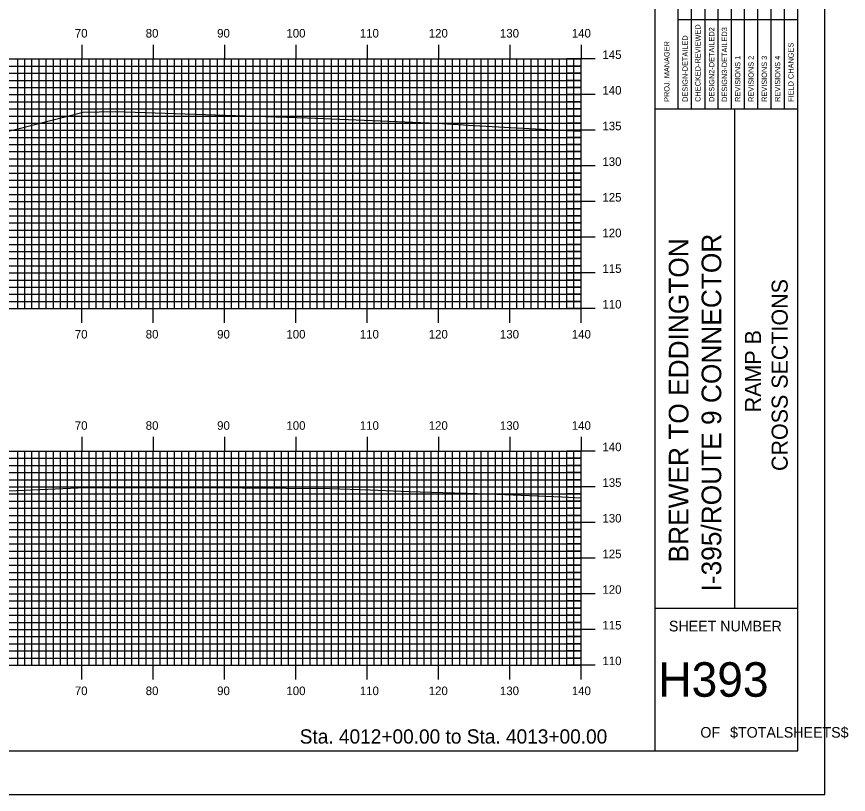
# Model space of a CAD drawing. Extents: x 852934 to 853277, y 364661 to 364881.
# Drawn here: x 853160.6 to 853277.3, y 364661.3 to 364770.3 of the extents above; entities that cross this region are included whole.
import ezdxf

# ---------------------------------------------------------------- set-up
doc = ezdxf.new("R2010")
doc.units = 0
for name, color, linetype in [('BORDER', 7, 'Continuous'), ('H_V ANNOTATION', 7, 'Continuous'), ('MAJOR', 7, 'Continuous'), ('MINOR', 7, 'Continuous'), ('PLOT BOUNDARY', 7, 'Continuous'), ('S_Roadway_Centerline', 7, 'Continuous')]:
    doc.layers.add(name, color=color, linetype=linetype)

msp = doc.modelspace()

# ---------------------------------------------------------------- linework, layer by layer
at = {"layer": 'BORDER'}
for p, q in [((853250.18, 364667.37), (853250.18, 364877.37)), ((853250.18, 364757.38), (853270.18, 364757.38)), ((853261.36, 364687.38), (853261.36, 364757.38)), ((853250.18, 364687.38), (853270.18, 364687.38))]:
    msp.add_line(p, q, dxfattribs=at)
msp.add_lwpolyline([(852950.18, 364667.37), (853270.18, 364667.37), (853270.18, 364877.37), (852950.18, 364877.37)], close=True, dxfattribs=at)
for points in [[(853255.28, 364757.38), (853255.28, 364792.38)], [(853257.14, 364792.38), (853257.14, 364757.38)], [(853259, 364757.38), (853259, 364792.38)], [(853260.87, 364757.38), (853260.87, 364792.38)], [(853262.73, 364757.38), (853262.73, 364792.38)], [(853264.59, 364757.38), (853264.59, 364792.38)], [(853266.46, 364757.38), (853266.46, 364792.38)], [(853268.32, 364757.38), (853268.32, 364792.38)], [(853253.41, 364757.38), (853253.41, 364790.96)], [(853253.41, 364769.88), (853270.18, 364769.88)]]:
    msp.add_lwpolyline(points, dxfattribs=at)
at = {"layer": 'MAJOR'}
for p, q in [((853169.78, 364766.37), (853169.78, 364764.37)), ((853179.78, 364766.37), (853179.78, 364764.37)), ((853189.78, 364766.37), (853189.78, 364764.37)), ((853199.78, 364766.37), (853199.78, 364764.37)), ((853209.78, 364766.37), (853209.78, 364764.37)), ((853219.78, 364766.37), (853219.78, 364764.37)), ((853229.78, 364766.37), (853229.78, 364764.37)), ((853239.78, 364766.37), (853239.78, 364764.37)), ((852959.78, 364764.37), (853239.78, 364764.37)), ((852959.78, 364764.37), (853239.78, 364764.37)), ((853169.78, 364729.37), (853169.78, 364764.37)), ((853179.78, 364729.37), (853179.78, 364764.37)), ((853189.78, 364729.37), (853189.78, 364764.37)), ((853199.78, 364729.37), (853199.78, 364764.37)), ((853209.78, 364729.37), (853209.78, 364764.37)), ((853219.78, 364729.37), (853219.78, 364764.37)), ((853229.78, 364729.37), (853229.78, 364764.37)), ((853241.79, 364764.37), (853237.78, 364764.37)), ((853239.78, 364729.37), (853239.78, 364764.37)), ((853239.78, 364729.37), (853239.78, 364764.37)), ((852959.78, 364759.37), (853239.78, 364759.37)), ((853241.79, 364759.37), (853237.78, 364759.37)), ((852959.78, 364754.37), (853239.78, 364754.37)), ((853241.79, 364754.37), (853237.78, 364754.37)), ((852959.78, 364749.37), (853239.78, 364749.37)), ((853241.79, 364749.37), (853237.78, 364749.37)), ((852959.78, 364744.37), (853239.78, 364744.37)), ((853241.79, 364744.37), (853237.78, 364744.37)), ((852959.78, 364739.37), (853239.78, 364739.37)), ((853241.79, 364739.37), (853237.78, 364739.37)), ((852959.78, 364734.37), (853239.78, 364734.37)), ((853241.79, 364734.37), (853237.78, 364734.37)), ((852959.78, 364729.37), (853239.78, 364729.37)), ((852959.78, 364729.37), (853239.78, 364729.37)), ((853169.78, 364727.37), (853169.78, 364729.37)), ((853179.78, 364727.37), (853179.78, 364729.37)), ((853189.78, 364727.37), (853189.78, 364729.37)), ((853199.78, 364727.37), (853199.78, 364729.37)), ((853209.78, 364727.37), (853209.78, 364729.37)), ((853219.78, 364727.37), (853219.78, 364729.37)), ((853229.78, 364727.37), (853229.78, 364729.37)), ((853241.79, 364729.37), (853237.78, 364729.37)), ((853239.78, 364727.37), (853239.78, 364729.37)), ((853169.78, 364711.37), (853169.78, 364709.37)), ((853179.78, 364711.37), (853179.78, 364709.37)), ((853189.78, 364711.37), (853189.78, 364709.37)), ((853199.78, 364711.37), (853199.78, 364709.37)), ((853209.78, 364711.37), (853209.78, 364709.37)), ((853219.78, 364711.37), (853219.78, 364709.37)), ((853229.78, 364711.37), (853229.78, 364709.37)), ((853239.78, 364711.37), (853239.78, 364709.37)), ((852959.78, 364709.37), (853239.78, 364709.37)), ((852959.78, 364709.37), (853239.78, 364709.37)), ((853169.78, 364679.37), (853169.78, 364709.37)), ((853179.78, 364679.37), (853179.78, 364709.37)), ((853189.78, 364679.37), (853189.78, 364709.37)), ((853199.78, 364679.37), (853199.78, 364709.37)), ((853209.78, 364679.37), (853209.78, 364709.37)), ((853219.78, 364679.37), (853219.78, 364709.37)), ((853229.78, 364679.37), (853229.78, 364709.37)), ((853241.79, 364709.37), (853237.78, 364709.37)), ((853239.78, 364679.37), (853239.78, 364709.37)), ((853239.78, 364679.37), (853239.78, 364709.37)), ((852959.78, 364704.37), (853239.78, 364704.37)), ((853241.79, 364704.37), (853237.78, 364704.37)), ((852959.78, 364699.37), (853239.78, 364699.37)), ((853241.79, 364699.37), (853237.78, 364699.37)), ((852959.78, 364694.37), (853239.78, 364694.37)), ((853241.79, 364694.37), (853237.78, 364694.37)), ((852959.78, 364689.37), (853239.78, 364689.37)), ((853241.79, 364689.37), (853237.78, 364689.37)), ((852959.78, 364684.37), (853239.78, 364684.37)), ((853241.79, 364684.37), (853237.78, 364684.37)), ((852959.78, 364679.37), (853239.78, 364679.37)), ((852959.78, 364679.37), (853239.78, 364679.37)), ((853169.78, 364677.37), (853169.78, 364679.37)), ((853179.78, 364677.37), (853179.78, 364679.37)), ((853189.78, 364677.37), (853189.78, 364679.37)), ((853199.78, 364677.37), (853199.78, 364679.37)), ((853209.78, 364677.37), (853209.78, 364679.37)), ((853219.78, 364677.37), (853219.78, 364679.37)), ((853229.78, 364677.37), (853229.78, 364679.37)), ((853241.79, 364679.37), (853237.78, 364679.37)), ((853239.78, 364677.37), (853239.78, 364679.37))]:
    msp.add_line(p, q, dxfattribs=at)
at = {"layer": 'MINOR'}
for p, q in [((853160.78, 364729.37), (853160.78, 364764.37)), ((853161.78, 364729.37), (853161.78, 364764.37)), ((853162.78, 364729.37), (853162.78, 364764.37)), ((853163.78, 364729.37), (853163.78, 364764.37)), ((853164.78, 364729.37), (853164.78, 364764.37)), ((853165.78, 364729.37), (853165.78, 364764.37)), ((853166.78, 364729.37), (853166.78, 364764.37)), ((853167.78, 364729.37), (853167.78, 364764.37)), ((853168.78, 364729.37), (853168.78, 364764.37)), ((853170.78, 364729.37), (853170.78, 364764.37)), ((853171.78, 364729.37), (853171.78, 364764.37)), ((853172.78, 364729.37), (853172.78, 364764.37)), ((853173.78, 364729.37), (853173.78, 364764.37)), ((853174.78, 364729.37), (853174.78, 364764.37)), ((853175.78, 364729.37), (853175.78, 364764.37)), ((853176.78, 364729.37), (853176.78, 364764.37)), ((853177.78, 364729.37), (853177.78, 364764.37)), ((853178.78, 364729.37), (853178.78, 364764.37)), ((853180.78, 364729.37), (853180.78, 364764.37)), ((853181.78, 364729.37), (853181.78, 364764.37)), ((853182.78, 364729.37), (853182.78, 364764.37)), ((853183.78, 364729.37), (853183.78, 364764.37)), ((853184.78, 364729.37), (853184.78, 364764.37)), ((853185.78, 364729.37), (853185.78, 364764.37)), ((853186.78, 364729.37), (853186.78, 364764.37)), ((853187.78, 364729.37), (853187.78, 364764.37)), ((853188.78, 364729.37), (853188.78, 364764.37)), ((853190.78, 364729.37), (853190.78, 364764.37)), ((853191.78, 364729.37), (853191.78, 364764.37)), ((853192.78, 364729.37), (853192.78, 364764.37)), ((853193.78, 364729.37), (853193.78, 364764.37)), ((853194.78, 364729.37), (853194.78, 364764.37)), ((853195.78, 364729.37), (853195.78, 364764.37)), ((853196.78, 364729.37), (853196.78, 364764.37)), ((853197.78, 364729.37), (853197.78, 364764.37)), ((853198.78, 364729.37), (853198.78, 364764.37)), ((853200.78, 364729.37), (853200.78, 364764.37)), ((853201.78, 364729.37), (853201.78, 364764.37)), ((853202.78, 364729.37), (853202.78, 364764.37)), ((853203.78, 364729.37), (853203.78, 364764.37)), ((853204.78, 364729.37), (853204.78, 364764.37)), ((853205.78, 364729.37), (853205.78, 364764.37)), ((853206.78, 364729.37), (853206.78, 364764.37)), ((853207.78, 364729.37), (853207.78, 364764.37)), ((853208.78, 364729.37), (853208.78, 364764.37)), ((853210.78, 364729.37), (853210.78, 364764.37)), ((853211.78, 364729.37), (853211.78, 364764.37)), ((853212.78, 364729.37), (853212.78, 364764.37)), ((853213.78, 364729.37), (853213.78, 364764.37)), ((853214.78, 364729.37), (853214.78, 364764.37)), ((853215.78, 364729.37), (853215.78, 364764.37)), ((853216.78, 364729.37), (853216.78, 364764.37)), ((853217.78, 364729.37), (853217.78, 364764.37)), ((853218.78, 364729.37), (853218.78, 364764.37)), ((853220.78, 364729.37), (853220.78, 364764.37)), ((853221.78, 364729.37), (853221.78, 364764.37)), ((853222.78, 364729.37), (853222.78, 364764.37)), ((853223.78, 364729.37), (853223.78, 364764.37)), ((853224.78, 364729.37), (853224.78, 364764.37)), ((853225.78, 364729.37), (853225.78, 364764.37)), ((853226.78, 364729.37), (853226.78, 364764.37)), ((853227.78, 364729.37), (853227.78, 364764.37)), ((853228.78, 364729.37), (853228.78, 364764.37)), ((853230.78, 364729.37), (853230.78, 364764.37)), ((853231.78, 364729.37), (853231.78, 364764.37)), ((853232.78, 364729.37), (853232.78, 364764.37)), ((853233.78, 364729.37), (853233.78, 364764.37)), ((853234.78, 364729.37), (853234.78, 364764.37)), ((853235.78, 364729.37), (853235.78, 364764.37)), ((853236.78, 364729.37), (853236.78, 364764.37)), ((853237.78, 364729.37), (853237.78, 364764.37)), ((853238.78, 364729.37), (853238.78, 364764.37)), ((852959.78, 364763.37), (853239.78, 364763.37)), ((853239.78, 364763.37), (853237.78, 364763.37)), ((852959.78, 364762.37), (853239.78, 364762.37)), ((853239.78, 364762.37), (853237.78, 364762.37)), ((852959.78, 364761.37), (853239.78, 364761.37)), ((853239.78, 364761.37), (853237.78, 364761.37)), ((852959.78, 364760.37), (853239.78, 364760.37)), ((853239.78, 364760.37), (853237.78, 364760.37)), ((852959.78, 364758.37), (853239.78, 364758.37)), ((852959.78, 364757.37), (853239.78, 364757.37)), ((853239.78, 364758.37), (853237.78, 364758.37)), ((853239.78, 364757.37), (853237.78, 364757.37)), ((852959.78, 364756.37), (853239.78, 364756.37)), ((853239.78, 364756.37), (853237.78, 364756.37)), ((852959.78, 364755.37), (853239.78, 364755.37)), ((853239.78, 364755.37), (853237.78, 364755.37)), ((852959.78, 364753.37), (853239.78, 364753.37)), ((853239.78, 364753.37), (853237.78, 364753.37)), ((852959.78, 364752.37), (853239.78, 364752.37)), ((853239.78, 364752.37), (853237.78, 364752.37)), ((852959.78, 364751.37), (853239.78, 364751.37)), ((852959.78, 364750.37), (853239.78, 364750.37)), ((853239.78, 364751.37), (853237.78, 364751.37)), ((853239.78, 364750.37), (853237.78, 364750.37)), ((852959.78, 364748.37), (853239.78, 364748.37)), ((853239.78, 364748.37), (853237.78, 364748.37)), ((852959.78, 364747.37), (853239.78, 364747.37)), ((853239.78, 364747.37), (853237.78, 364747.37)), ((852959.78, 364746.37), (853239.78, 364746.37)), ((853239.78, 364746.37), (853237.78, 364746.37)), ((852959.78, 364745.37), (853239.78, 364745.37)), ((853239.78, 364745.37), (853237.78, 364745.37)), ((852959.78, 364743.37), (853239.78, 364743.37)), ((853239.78, 364743.37), (853237.78, 364743.37)), ((852959.78, 364742.37), (853239.78, 364742.37)), ((853239.78, 364742.37), (853237.78, 364742.37)), ((852959.78, 364741.37), (853239.78, 364741.37)), ((853239.78, 364741.37), (853237.78, 364741.37)), ((852959.78, 364740.37), (853239.78, 364740.37)), ((853239.78, 364740.37), (853237.78, 364740.37)), ((852959.78, 364738.37), (853239.78, 364738.37)), ((853239.78, 364738.37), (853237.78, 364738.37)), ((852959.78, 364737.37), (853239.78, 364737.37)), ((852959.78, 364736.37), (853239.78, 364736.37)), ((853239.78, 364737.37), (853237.78, 364737.37)), ((853239.78, 364736.37), (853237.78, 364736.37)), ((852959.78, 364735.37), (853239.78, 364735.37)), ((853239.78, 364735.37), (853237.78, 364735.37)), ((852959.78, 364733.37), (853239.78, 364733.37)), ((853239.78, 364733.37), (853237.78, 364733.37)), ((852959.78, 364732.37), (853239.78, 364732.37)), ((853239.78, 364732.37), (853237.78, 364732.37)), ((852959.78, 364731.37), (853239.78, 364731.37)), ((853239.78, 364731.37), (853237.78, 364731.37)), ((852959.78, 364730.37), (853239.78, 364730.37)), ((853239.78, 364730.37), (853237.78, 364730.37)), ((852959.78, 364708.37), (853239.78, 364708.37)), ((853160.78, 364679.37), (853160.78, 364709.37)), ((853161.78, 364679.37), (853161.78, 364709.37)), ((853162.78, 364679.37), (853162.78, 364709.37)), ((853163.78, 364679.37), (853163.78, 364709.37)), ((853164.78, 364679.37), (853164.78, 364709.37)), ((853165.78, 364679.37), (853165.78, 364709.37)), ((853166.78, 364679.37), (853166.78, 364709.37)), ((853167.78, 364679.37), (853167.78, 364709.37)), ((853168.78, 364679.37), (853168.78, 364709.37)), ((853170.78, 364679.37), (853170.78, 364709.37)), ((853171.78, 364679.37), (853171.78, 364709.37)), ((853172.78, 364679.37), (853172.78, 364709.37)), ((853173.78, 364679.37), (853173.78, 364709.37)), ((853174.78, 364679.37), (853174.78, 364709.37)), ((853175.78, 364679.37), (853175.78, 364709.37)), ((853176.78, 364679.37), (853176.78, 364709.37)), ((853177.78, 364679.37), (853177.78, 364709.37)), ((853178.78, 364679.37), (853178.78, 364709.37)), ((853180.78, 364679.37), (853180.78, 364709.37)), ((853181.78, 364679.37), (853181.78, 364709.37)), ((853182.78, 364679.37), (853182.78, 364709.37)), ((853183.78, 364679.37), (853183.78, 364709.37)), ((853184.78, 364679.37), (853184.78, 364709.37)), ((853185.78, 364679.37), (853185.78, 364709.37)), ((853186.78, 364679.37), (853186.78, 364709.37)), ((853187.78, 364679.37), (853187.78, 364709.37)), ((853188.78, 364679.37), (853188.78, 364709.37)), ((853190.78, 364679.37), (853190.78, 364709.37)), ((853191.78, 364679.37), (853191.78, 364709.37)), ((853192.78, 364679.37), (853192.78, 364709.37)), ((853193.78, 364679.37), (853193.78, 364709.37)), ((853194.78, 364679.37), (853194.78, 364709.37)), ((853195.78, 364679.37), (853195.78, 364709.37)), ((853196.78, 364679.37), (853196.78, 364709.37)), ((853197.78, 364679.37), (853197.78, 364709.37)), ((853198.78, 364679.37), (853198.78, 364709.37)), ((853200.78, 364679.37), (853200.78, 364709.37)), ((853201.78, 364679.37), (853201.78, 364709.37)), ((853202.78, 364679.37), (853202.78, 364709.37)), ((853203.78, 364679.37), (853203.78, 364709.37)), ((853204.78, 364679.37), (853204.78, 364709.37)), ((853205.78, 364679.37), (853205.78, 364709.37)), ((853206.78, 364679.37), (853206.78, 364709.37)), ((853207.78, 364679.37), (853207.78, 364709.37)), ((853208.78, 364679.37), (853208.78, 364709.37)), ((853210.78, 364679.37), (853210.78, 364709.37)), ((853211.78, 364679.37), (853211.78, 364709.37)), ((853212.78, 364679.37), (853212.78, 364709.37)), ((853213.78, 364679.37), (853213.78, 364709.37)), ((853214.78, 364679.37), (853214.78, 364709.37)), ((853215.78, 364679.37), (853215.78, 364709.37)), ((853216.78, 364679.37), (853216.78, 364709.37)), ((853217.78, 364679.37), (853217.78, 364709.37)), ((853218.78, 364679.37), (853218.78, 364709.37)), ((853220.78, 364679.37), (853220.78, 364709.37)), ((853221.78, 364679.37), (853221.78, 364709.37)), ((853222.78, 364679.37), (853222.78, 364709.37)), ((853223.78, 364679.37), (853223.78, 364709.37)), ((853224.78, 364679.37), (853224.78, 364709.37)), ((853225.78, 364679.37), (853225.78, 364709.37)), ((853226.78, 364679.37), (853226.78, 364709.37)), ((853227.78, 364679.37), (853227.78, 364709.37)), ((853228.78, 364679.37), (853228.78, 364709.37)), ((853230.78, 364679.37), (853230.78, 364709.37)), ((853231.78, 364679.37), (853231.78, 364709.37)), ((853232.78, 364679.37), (853232.78, 364709.37)), ((853233.78, 364679.37), (853233.78, 364709.37)), ((853234.78, 364679.37), (853234.78, 364709.37)), ((853235.78, 364679.37), (853235.78, 364709.37)), ((853236.78, 364679.37), (853236.78, 364709.37)), ((853237.78, 364679.37), (853237.78, 364709.37)), ((853239.78, 364708.37), (853237.78, 364708.37)), ((853238.78, 364679.37), (853238.78, 364709.37)), ((852959.78, 364707.37), (853239.78, 364707.37)), ((853239.78, 364707.37), (853237.78, 364707.37)), ((852959.78, 364706.37), (853239.78, 364706.37)), ((853239.78, 364706.37), (853237.78, 364706.37)), ((852959.78, 364705.37), (853239.78, 364705.37)), ((853239.78, 364705.37), (853237.78, 364705.37)), ((852959.78, 364703.37), (853239.78, 364703.37)), ((853239.78, 364703.37), (853237.78, 364703.37)), ((852959.78, 364702.37), (853239.78, 364702.37)), ((852959.78, 364701.37), (853239.78, 364701.37)), ((853239.78, 364702.37), (853237.78, 364702.37)), ((853239.78, 364701.37), (853237.78, 364701.37)), ((852959.78, 364700.37), (853239.78, 364700.37)), ((853239.78, 364700.37), (853237.78, 364700.37)), ((852959.78, 364698.37), (853239.78, 364698.37)), ((853239.78, 364698.37), (853237.78, 364698.37)), ((852959.78, 364697.37), (853239.78, 364697.37)), ((853239.78, 364697.37), (853237.78, 364697.37)), ((852959.78, 364696.37), (853239.78, 364696.37)), ((853239.78, 364696.37), (853237.78, 364696.37)), ((852959.78, 364695.37), (853239.78, 364695.37)), ((853239.78, 364695.37), (853237.78, 364695.37)), ((852959.78, 364693.37), (853239.78, 364693.37)), ((853239.78, 364693.37), (853237.78, 364693.37)), ((852959.78, 364692.37), (853239.78, 364692.37)), ((853239.78, 364692.37), (853237.78, 364692.37)), ((852959.78, 364691.37), (853239.78, 364691.37)), ((853239.78, 364691.37), (853237.78, 364691.37)), ((852959.78, 364690.37), (853239.78, 364690.37)), ((853239.78, 364690.37), (853237.78, 364690.37)), ((852959.78, 364688.37), (853239.78, 364688.37)), ((853239.78, 364688.37), (853237.78, 364688.37)), ((852959.78, 364687.37), (853239.78, 364687.37)), ((852959.78, 364686.37), (853239.78, 364686.37)), ((853239.78, 364687.37), (853237.78, 364687.37)), ((853239.78, 364686.37), (853237.78, 364686.37)), ((852959.78, 364685.37), (853239.78, 364685.37)), ((853239.78, 364685.37), (853237.78, 364685.37)), ((852959.78, 364683.37), (853239.78, 364683.37)), ((853239.78, 364683.37), (853237.78, 364683.37)), ((852959.78, 364682.37), (853239.78, 364682.37)), ((853239.78, 364682.37), (853237.78, 364682.37)), ((852959.78, 364681.37), (853239.78, 364681.37)), ((853239.78, 364681.37), (853237.78, 364681.37)), ((852959.78, 364680.37), (853239.78, 364680.37)), ((853239.78, 364680.37), (853237.78, 364680.37))]:
    msp.add_line(p, q, dxfattribs=at)
at = {"layer": 'PLOT BOUNDARY'}
msp.add_lwpolyline([(852933.99, 364661.25), (853273.99, 364661.25), (853273.99, 364881.25), (852933.99, 364881.25)], close=True, dxfattribs=at)
at = {"layer": 'S_Roadway_Centerline'}
for points in [[(853151.22, 364752.16), (853169.96, 364756.93), (853174.43, 364756.98), (853195.53, 364756.29), (853198.48, 364756.19), (853201.42, 364756.11), (853219.62, 364755.38), (853224.76, 364755.02), (853237.68, 364754.35), (853239.78, 364754.25)], [(853156.26, 364703.66), (853169.25, 364704.21), (853186.17, 364704.29), (853204.54, 364704.12), (853210.2, 364703.93), (853215.62, 364703.73), (853226.79, 364703.39), (853237.16, 364702.97), (853239.78, 364702.82)]]:
    msp.add_lwpolyline(points, dxfattribs=at)

# ---------------------------------------------------------------- texts
at = {"layer": 'BORDER'}
for s, height, p in [('CHECKED-REVIEWED', 0.7455, (853256.54, 364758.35)), ('DESIGN2-DETAILED2', 0.7455, (853258.48, 364758.35)), ('DESIGN3-DETAILED3', 0.7455, (853260.27, 364758.35)), ('DESIGN-DETAILED', 0.7455, (853254.75, 364758.35)), ('PROJ. MANAGER', 0.7455, (853252.19, 364758.35)), ('FIELD CHANGES', 0.7455, (853269.59, 364758.35)), ('REVISIONS 1', 0.7455, (853262.13, 364758.35)), ('REVISIONS 2', 0.7455, (853264, 364758.35)), ('REVISIONS 3', 0.7455, (853265.86, 364758.35)), ('REVISIONS 4', 0.7455, (853267.72, 364758.35)), ('BREWER TO EDDINGTON', 2.7557, (853254.85, 364693.78)), ('I-395/ROUTE 9 CONNECTOR', 2.7557, (853259.45, 364689.7)), ('CROSS SECTIONS', 2.25, (853268.77, 364706.59)), ('RAMP B', 2.25, (853265.02, 364714.82))]:
    msp.add_text(s, height=height, rotation=90, dxfattribs=at).set_placement(p)
for s, height, p in [('SHEET NUMBER', 1.4905, (853252.11, 364684.1)), ('H393', 4.839, (853250.62, 364674.94)), ('OF', 1.491, (853256.52, 364669.2)), ('$TOTALSHEETS$', 1.4905, (853260.69, 364669.2))]:
    msp.add_text(s, height=height, dxfattribs=at).set_placement(p)
at = {"layer": 'H_V ANNOTATION'}
for s, height, p in [('70', 1.2, (853168.79, 364767.37)), ('80', 1.2, (853178.73, 364767.37)), ('90', 1.2, (853188.75, 364767.37)), ('100', 1.2, (853198.46, 364767.37)), ('110', 1.2, (853208.76, 364767.37)), ('120', 1.2, (853218.42, 364767.37)), ('130', 1.2, (853228.41, 364767.37)), ('140', 1.2, (853238.49, 364767.37)), ('145', 1.2, (853242.78, 364764.37)), ('140', 1.2, (853242.78, 364759.37)), ('135', 1.2, (853242.78, 364754.37)), ('130', 1.2, (853242.78, 364749.37)), ('125', 1.2, (853242.78, 364744.37)), ('120', 1.2, (853242.78, 364739.37)), ('115', 1.2, (853242.78, 364734.37)), ('110', 1.2, (853242.78, 364729.37)), ('70', 1.2, (853168.79, 364725.17)), ('80', 1.2, (853178.73, 364725.17)), ('90', 1.2, (853188.75, 364725.17)), ('100', 1.2, (853198.46, 364725.17)), ('110', 1.2, (853208.76, 364725.17)), ('120', 1.2, (853218.42, 364725.17)), ('130', 1.2, (853228.41, 364725.17)), ('140', 1.2, (853238.49, 364725.17)), ('70', 1.2, (853168.79, 364712.37)), ('80', 1.2, (853178.73, 364712.37)), ('90', 1.2, (853188.75, 364712.37)), ('100', 1.2, (853198.46, 364712.37)), ('110', 1.2, (853208.76, 364712.37)), ('120', 1.2, (853218.42, 364712.37)), ('130', 1.2, (853228.41, 364712.37)), ('140', 1.2, (853238.49, 364712.37)), ('140', 1.2, (853242.78, 364709.37)), ('135', 1.2, (853242.78, 364704.37)), ('130', 1.2, (853242.78, 364699.37)), ('125', 1.2, (853242.78, 364694.37)), ('120', 1.2, (853242.78, 364689.37)), ('115', 1.2, (853242.78, 364684.37)), ('110', 1.2, (853242.78, 364679.37)), ('70', 1.2, (853168.79, 364675.17)), ('80', 1.2, (853178.73, 364675.17)), ('90', 1.2, (853188.75, 364675.17)), ('100', 1.2, (853198.46, 364675.17)), ('110', 1.2, (853208.76, 364675.17)), ('120', 1.2, (853218.42, 364675.17)), ('130', 1.2, (853228.41, 364675.17)), ('140', 1.2, (853238.49, 364675.17)), ('Sta. 4012+00.00 to Sta. 4013+00.00', 2.0004, (853200.33, 364668.37))]:
    msp.add_text(s, height=height, dxfattribs=at).set_placement(p)

doc.saveas('drawing.dxf')
